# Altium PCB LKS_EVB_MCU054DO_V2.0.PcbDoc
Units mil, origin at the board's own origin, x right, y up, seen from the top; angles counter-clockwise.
Board outline 2625 x 1560 mil, 2 copper layers (Top Layer, Bottom Layer); 34 components, 56 nets, 171 pads, 56 vias.
Unrouted connection lines stored in the file: 4.
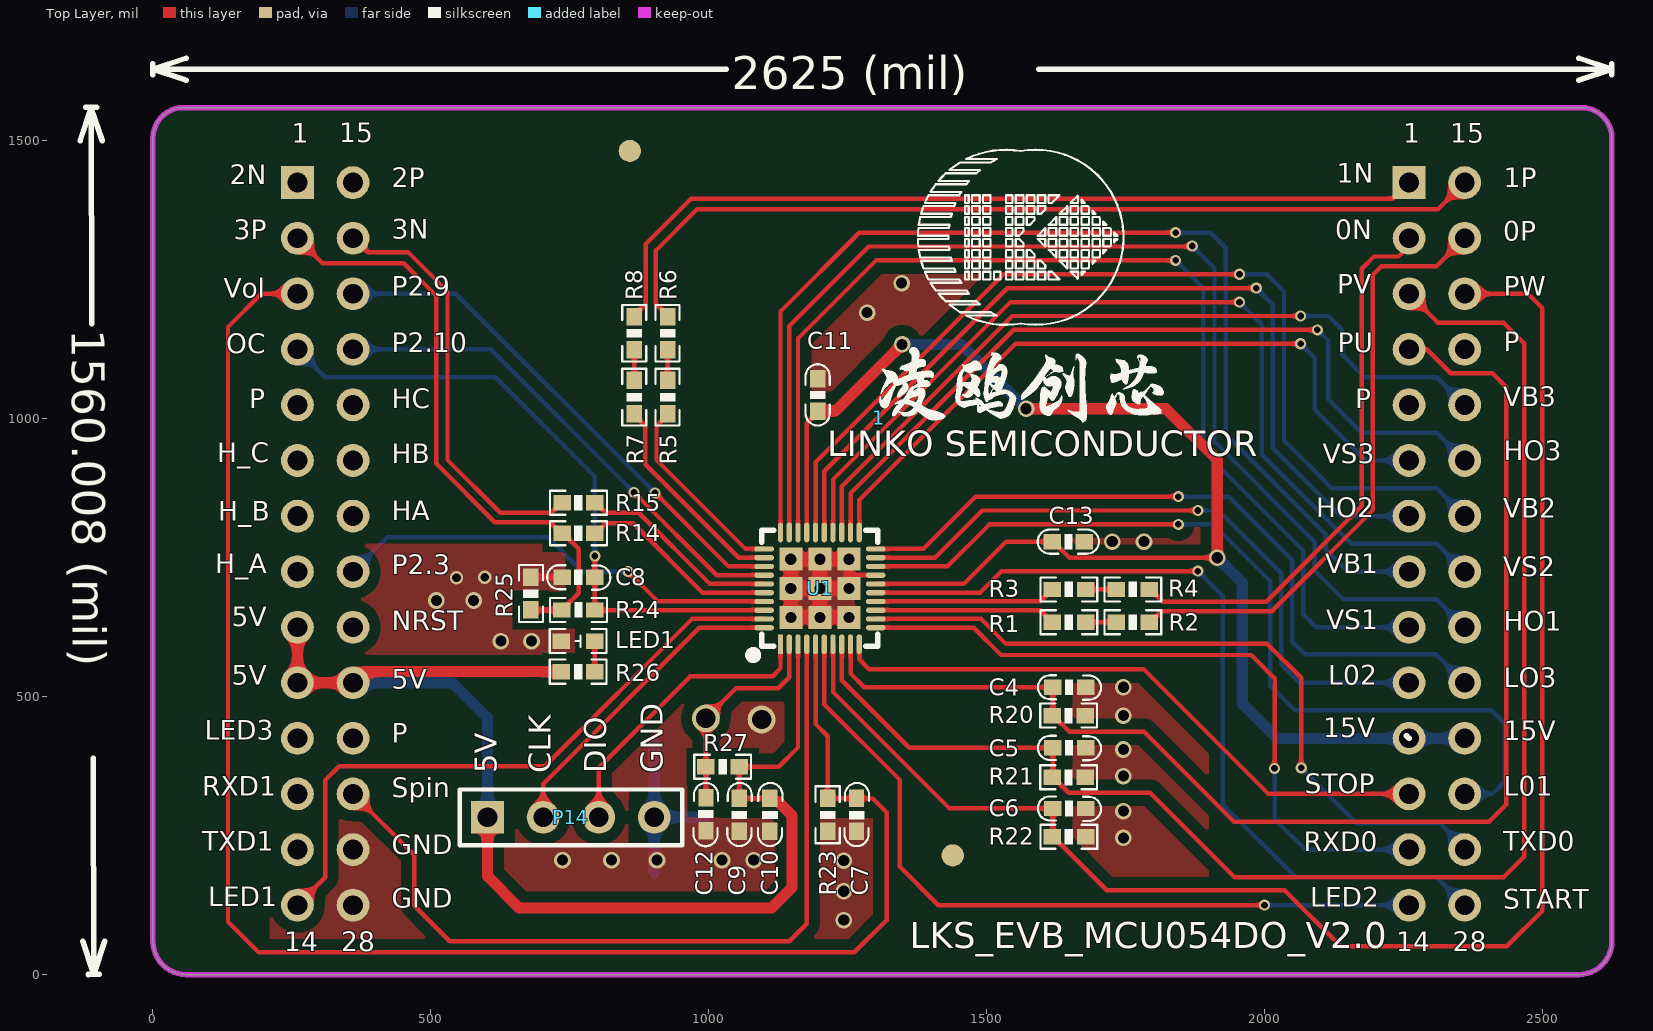
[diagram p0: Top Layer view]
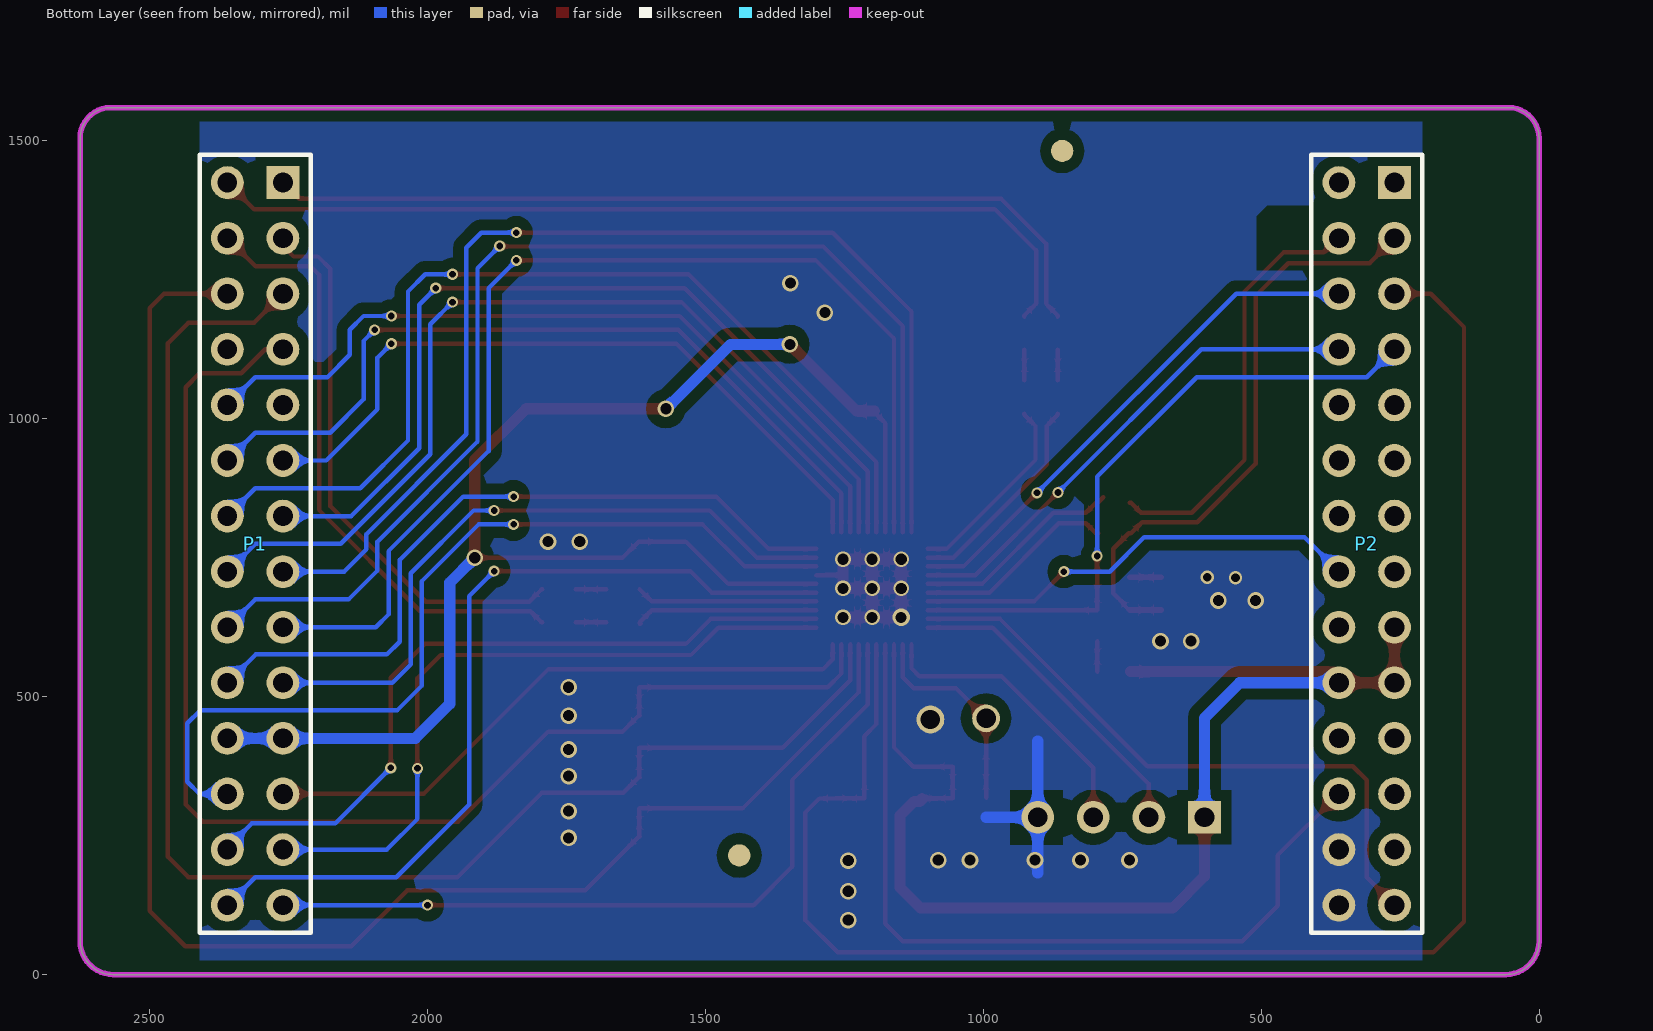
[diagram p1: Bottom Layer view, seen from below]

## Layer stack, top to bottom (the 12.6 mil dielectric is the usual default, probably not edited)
Top Solder: solder mask 0.4, Solder Resist, Dk 3.5
Top Layer: signal copper 1.4
Dielectric1: dielectric 12.6, FR-4, Dk 4.8
Bottom Layer: signal copper 1.4
Bottom Solder: solder mask 0.4, Solder Resist, Dk 3.5

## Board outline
0,60 ccw(c60,60) 60,0 2565,0 ccw(c2565,60) 2625,60 2625,1505 ccw(c2570,1505) 2570,1560 55,1560 ccw(c55,1505) 0,1505

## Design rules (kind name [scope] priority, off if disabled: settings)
Clearance Clearance_1 [InPolygon] p1: gap=20 ignorepadtopadclearanceinfootprint=FALSE
Clearance [All] p2: gap=6 ignorepadtopadclearanceinfootprint=FALSE
ComponentClearance [All] p1: gap=0 collisioncheckmode=3 verticalgap=0 showdistances=FALSE
FabricationTestpoint [(IsPad And (OnTopLayer Or OnBottomLayer))] p1: side=3 testpointundercomponent=TRUE minsize=40 maxsize=100 preferedsize=60 minholesize=0 maxholesize=40 preferedholesize=32 testpointgrid=1 allowsidetop=TRUE allowsidebottom=TRUE usegrid=TRUE gridtolerance=0.01
HoleSize [All] p1: absolutevalues=TRUE maxlimit=100 minlimit=0 maxpercent=80.000 minpercent=20.000
PolygonConnect [All] p1: connectstyle=Direct reliefconductorwidth=30 reliefentries=4 polygonreliefangle="90 Angle" airgapwidth=10
RoutingVias [All] p1: holewidth=28 width=50 viastyle="Through Hole" minholewidth=0 minwidth=10 maxholewidth=28 maxwidth=100
SilkToSolderMaskClearance SilkscreenOverComponentPads [IsPad] p1: minsilkscreentomaskgap=10 clearancetoexposedcopper=TRUE
SolderMaskExpansion [All] p1: expansion=4 istentingtop=FALSE
Width [All] p1: maxlimit=100 minlimit=2 preferedwidth=10
26 further rules are at their usual default settings.

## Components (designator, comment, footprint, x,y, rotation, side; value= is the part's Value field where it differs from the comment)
1 "LKS_sign" LKS_LOGO2 1306,1002 r0 top
C4 "1nF/16V" 0603C#1 1619,517 r0 top
C5 "1nF/16V" 0603C#1 1618.94,408 r0 top
C6 "1nF/16V" 0603C#1 1618.94,299 r0 top
C7 "100nF/50V" 0603C#1 1266,257.8 r90 top
C8 "1nF/50V" 0603C#1 736,715 r0 top
C9 "10uF/10V" 0603C#1 1055,258 r90 top
C10 "100nF/50V" 0603C#1 1110,257.94 r90 top
C11 "4.7uF/25V" 0603C#2 1196,1043 r270 top
C12 "100nF/50V" 0603C#1 995,318 r270 top
C13 "1uF/16V" 0603C#2 1647,779 r0 top
LED1 "LED" "LED 0603R" 765,600 r180 top
P1 "Header 14X2A" HDR2X14_CEN 2260,1425 r270 bottom locked
P2 "Header 14X2A" HDR2X14_CEN 260,1425 r270 bottom locked
P14 "Header 4" HDR1X4 602,283 r0 top
R1 "20K" 0603R#1 1648,634 r180 top value=K
R2 "20K" 0603R#1 1763,634 r180 top value=K
R3 "20K" 0603R#1 1648,693 r180 top value=K
R4 "20K" 0603R#1 1763,693 r180 top value=K
R5 "20K" 0603R#1 926,1039 r270 top value=K
R6 "20K" 0603R#1 926,1154 r270 top value=K
R7 "20K" 0603R#1 866,1039 r270 top value=K
R8 "20K" 0603R#1 866,1154 r270 top value=K
R14 "1K" 0603R#2 736.22,794 r0 top value=K
R15 "1K" 0603R#2 736.17,849 r0 top value=K
R20 "1K" 0603R#2 1618,466 r0 top value=K
R21 "1K" 0603R#2 1618,355 r0 top value=K
R22 "1K" 0603R#1 1648,248 r0 top value=K
R23 "1K" 0603R#2 1214,258 r90 top value=K
R24 "1K" 0603R#2 795,656 r180 top value=K
R25 "10R" 0603R#2 680,656 r90 top value=K
R26 "3.3K" 0603R#1 765,545 r180 top value=330
R27 "20K" 0603R#1 1025,374 r180 top value=K
U1 "LKS32MC054DOF6Q8" QFN40 1200,695 r90 top locked

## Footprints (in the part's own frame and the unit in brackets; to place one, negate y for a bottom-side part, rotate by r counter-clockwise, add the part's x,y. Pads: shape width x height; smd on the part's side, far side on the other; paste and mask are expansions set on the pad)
0603C#1 [mm]
  rect 0.8x0.7 smd: 1(0,0) 2(1.5,0)
  silkscreen extent -0.68,-0.57 2.21,0.55
0603C#2 [mm] "电容"
  rect 0.8x0.7 smd: 1(-0.737,0) 2(0.738,0)
  silkscreen extent -1.4,-0.55 1.4,0.55, body extent -0.8,-0.41 0.8,0.41, height 0.81
0603R#1 [mm] "电阻"
  rect 0.8x0.7 smd: 1(-0.762,0) 2(0.762,0)
  silkscreen extent -1.3,-0.55 1.3,0.55, body extent -0.8,-0.4 0.8,0.4, height 0.45
0603R#2 [mm]
  rect 0.8x0.7 smd: 1(0,0) 2(1.5,0)
  silkscreen extent -0.55,-0.55 2.05,0.55
HDR1X4 [mm] "Connector; Header; 4 Position"
  rect 1.5x1.5 hole 0.9: 1(0,0)
  round 1.5 hole 0.9: 2(2.54,0) 3(5.08,0) 4(7.62,0)
  silkscreen extent -1.27,-1.27 8.89,1.27
HDR2X14_CEN [mm] "Connector; Header; 14x2 Position"
  rect 1.5x1.5 hole 0.9: 1(0,0)
  round 1.5 hole 0.9: 2(2.54,0) 3(5.08,0) 4(7.62,0) 5(10.16,0) 6(12.7,0) 7(15.24,0) 8(17.78,0) 9(20.32,0) 10(22.86,0) 11(25.4,0) 12(27.94,0) 13(30.48,0) 14(33.02,0) 15(0,-2.54) 16(2.54,-2.54) 17(5.08,-2.54) 18(7.62,-2.54) 19(10.16,-2.54) 20(12.7,-2.54) 21(15.24,-2.54) 22(17.78,-2.54) 23(20.32,-2.54) 24(22.86,-2.54) 25(25.4,-2.54) 26(27.94,-2.54) 27(30.48,-2.54) 28(33.02,-2.54)
  silkscreen extent -1.27,-3.81 34.29,1.27
"LED 0603R" [mm] "LED"
  rect 0.8x0.7 smd: 1(-0.762,0) 2(0.762,0)
  silkscreen extent -1.3,-0.55 1.3,0.55, body extent -0.8,-0.4 0.8,0.4, height 0.47
LKS_LOGO2 [mil] "标?"
  silkscreen extent 70,167 440,482
QFN40 [mm] "LINKO-084D"
  rect 1.05x1.05 smd: 0(-1.33,-1.33) 0(-1.33,0) 0(-1.33,1.33) 0(0,1.33) 0(0,0) 0(0,-1.33) 0(1.33,-1.33) 0(1.33,0) 0(1.33,1.33)
  rect 0.9x0.24 smd: 1(-2.55,1.8)
  oval 0.9x0.24 smd: 2(-2.55,1.4) 3(-2.55,1) 4(-2.55,0.6) 5(-2.55,0.2) 6(-2.55,-0.2) 7(-2.55,-0.6) 8(-2.55,-1) 9(-2.55,-1.4) 10(-2.55,-1.8) 21(2.55,-1.8) 22(2.55,-1.4) 23(2.55,-1) 24(2.55,-0.6) 25(2.55,-0.2) 26(2.55,0.2) 27(2.55,0.6) 28(2.55,1) 29(2.55,1.4) 30(2.55,1.8)
  oval 0.24x0.9 smd: 11(-1.8,-2.55) 12(-1.4,-2.55) 13(-1,-2.55) 14(-0.6,-2.55) 15(-0.2,-2.55) 16(0.2,-2.55) 17(0.6,-2.55) 18(1,-2.55) 19(1.4,-2.55) 20(1.8,-2.55) 31(1.8,2.55) 32(1.4,2.55) 33(1,2.55) 34(0.6,2.55) 35(0.2,2.55) 36(-0.2,2.55) 37(-0.6,2.55) 38(-1,2.55) 39(-1.4,2.55) 40(-1.8,2.55)
  silkscreen extent -3.16,-2.65 2.65,3.16, body extent -3,-3 3,3, height 0.9

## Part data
C4 C5 C6 C13: library part CAP, "Capacitor"
C7 C8 C9 C10 C11 C12: library part C, "Capacitor"
LED1: "LED_Light"
P1 P2: "Header, 14-Pin, Dual row"
P14: "Header, 4-Pin"
R1 R2 R3 R4 R5 R6 R7 R8 R14 R15 R20 R21 R22 R23 R24 R25 R26 R27: library part Res, "Resistor"
U1: "芯片"

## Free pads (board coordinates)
  round 50 hole 35: 0(1095,459) 1(995,461)
  round 40 all layers, no hole: 3(858,1482) 5(1439.03,214.44)

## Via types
v1: diameter 30, hole 20, Top Layer to Bottom Layer, 25 vias
v2: diameter 20, hole 12, Top Layer to Bottom Layer, 20 vias
v3: diameter 28, hole 20, Top Layer to Bottom Layer, 8 vias
v4: diameter 23.62, hole 15.75, Top Layer to Bottom Layer, 2 vias
v5: diameter 31.5, hole 19.68, Top Layer to Bottom Layer, 1 vias

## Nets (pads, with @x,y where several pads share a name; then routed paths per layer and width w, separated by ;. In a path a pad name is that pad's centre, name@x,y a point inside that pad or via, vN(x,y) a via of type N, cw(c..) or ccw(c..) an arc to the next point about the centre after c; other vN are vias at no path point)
+5V: C9.2 C10.2 P2.9 P2.10 P2.24 P14.1 R26.2 R27.1 U1.3 | length 2324.2
  Top Layer w8: C10.2@1109.94,317.06 C9.2 R27.1 1126,374 1160.63,408.63 U1.3
  Top Layer w20: P2.9 P2.10 P2.24 380,545 R26.2 ; P14.1 602,177 659,120 1113,120 1150,157 1150,286 1124.75,311.25 1113.78,311.25 1109.94,315.09 C10.2@1109.94,317.06
  Bottom Layer w20: P2.24 539,525 602,462 P14.1
+15V: C11.2 C13.1 P1.11 P1.25 U1.16 U1.27 | length 2623
  Top Layer w8: U1.27 1176.38,992.35 1196,1011.98 C11.2 ; U1.16 1458.87,702.87 1535,779 C13.1 1619.97,779 1648.97,750 v1(1915,750)
  Top Layer w20: C11.2 1227.95,1013.95 v1(1348,1134) ; v1(1571,1018) 1823,1018 1915,926 v1(1915,750)
  Bottom Layer w20: v1(1348,1134) 1455,1134 v1(1571,1018) ; v1(1915,750) 1960,705 1960,487 2022,425 P1.11 P1.25
GND: C4.2 C5.2 C6.2 C7.1 C8.1 C9.1 C10.1 C11.1 C12.2 C13.2 LED1.2 P2.16 P2.27 P2.28 P14.4 pad.0 R15.1 R20.2 R21.2 R22.2 R23.1 R25.2 U1.0 U1.17 | length 1846.6
  Top Layer w8: P2.16 362.1,1325 387.1,1300 459,1300 530,1229 530,926 625,831 716.2,831 734.2,849 R15.1 ; R25.2 R25.2@680.06,715 ; 1252.36,718.62 U1.17
  Top Layer w10: R25.2@680.06,715 C8.1
  Top Layer w20: U1.0@1181.5,642.64 v3(1200,642.64) ; v3(1252.36,642.64) v3(1200,642.64) ; v3(1147.64,747.36) v5(1147.64,642.64) v3(1200,642.64) ; v3(1147.64,747.36) v3(1200,747.36) ; v3(1147.64,747.36) v3(1147.64,695) v3(1200,695) ; v3(1200,642.64) v3(1200,695) ; v3(1200,695) v3(1252.36,695) 1252.36,718.62 v3(1252.36,747.36) v3(1200,747.36) ; v3(1200,695) v3(1200,747.36)
  Bottom Layer w20: 902,183 P14.4 ; 902,420 P14.4 ; 995,283 P14.4
  other v1: 1243,98 1243,150 1243,205 737,206 825,206 907,206 1024,206 1081,206 1746,246 1746,294 1746,357 1746,405 1746,466 1746,517 626,600 681,600 510,673 577,673 1726,779 1783,779 1285,1191 1347,1244
  other v4: 546,714 597,715
HALL_U: P2.8
HALL_V: P2.7
HALL_W: P2.6
HO1: P1.23 U1.29 | length 2143.7
  Top Layer w8: U1.29 1144.88,1166.88 1288,1310 1869,1310 v2(1870,1311)
  Bottom Layer w8: v2(1870,1311) 1910,1271 1910,959 2090,779 2090,727 2142,675 2310,675 P1.23
HO2: P1.7 U1.25 | length 1619.9
  Top Layer w8: U1.25 1207.87,905.87 1537,1235 v2(1985,1235)
  Bottom Layer w8: v2(1985,1235) 2015,1205 2015,947 2137,825 P1.7
HO3: P1.20 U1.22 | length 1456.2
  Top Layer w8: U1.22 1255.12,866.12 1549,1160 v2(2095,1160)
  Bottom Layer w8: v2(2095,1160) 2115,1140 2115,1035 2175,975 2310,975 P1.20
HU: P2.21
HV: P2.20
HW: P2.19
LED1: P2.14 U1.39 | length 1155.4
  Top Layer w8: P2.14 310,175 310,350 335,375 705,375 969.88,639.88 U1.39
LED2: P1.14 U1.6 | length 1401.6
  Top Layer w8: U1.6 1207.87,486.13 1344,350 1344,194 1413,125 v2(2000,125)
  Bottom Layer w8: v2(2000,125) P1.14
LO1: P1.26 U1.18 | length 1607.5
  Top Layer w8: U1.18 1429.37,734.37 1505,810 v2(1845,810)
  Bottom Layer w8: v2(1845,810) 1908,810 2010,708 2010,520 2054,476 2408,476 2432,452 2432,347 2410,325 P1.26
LO2: P1.10 U1.19 | length 1219.2
  Top Layer w8: U1.19 1407.12,750.12 1492,835 v2(1880,835)
  Bottom Layer w8: v2(1880,835) 1917,835 2030,722 2030,558 2063,525 P1.10
LO3: P1.24 U1.20 | length 1323.5
  Top Layer w8: U1.20 1385.87,765.87 1480,860 v2(1845,860)
  Bottom Layer w8: v2(1845,860) 1936,860 2050,746 2050,599 2073,576 2309,576 P1.24
NetLED1_1: LED1.1 R26.1 | length 55
  Top Layer w8: R26.1 LED1.1
NetR1_1: R1.1 R2.2 | length 55
  Top Layer w8: R1.1 R2.2
NetR3_1: R3.1 R4.2 | length 55
  Top Layer w8: R3.1 R4.2
NetR5_1: R5.1 R6.2 | length 55
  Top Layer w8: R5.1 R6.2
NetR7_1: R7.1 R8.2 | length 55
  Top Layer w8: R7.1 R8.2
NRST: C12.1 pad.1 R27.2 U1.2 | length 383.2
  Top Layer w8: C12.1 R27.2 pad.1 1049,515 1125,515 1144.88,534.88 U1.2
OC: C8.2 P2.4 R24.1 U1.38 | length 1174.7
  Top Layer w8: v2(795,753) 795,715.06 C8.2 795,714.94 R24.1 795.37,655.63 U1.38
  Bottom Layer w8: P2.4 310,1075 616,1075 795,896 v2(795,753)
OPA0_IN: R7.2 U1.32 | length 382.4
  Top Layer w8: R7.2 866,1007.03 886,987.03 886,918 1053.88,750.12 U1.32
OPA0_IP: R5.2 U1.31 | length 351.2
  Top Layer w8: R5.2 926,1007.03 906,987.03 906,926 1066.13,765.87 U1.31
OPA1_IN: R15.2 U1.35 | length 378.2
  Top Layer w8: R15.2@784,858.78 793.78,849 R15.2 ; R15.2@797.19,849 815.19,831 874,831 1002.13,702.87 U1.35
OPA1_IP: R14.2 U1.36 | length 365.5
  Top Layer w8: R14.2@793.31,794 R14.2 797.24,794 815.24,812 864,812 988.87,687.13 U1.36
OPA2_IN: R3.2 U1.14 | length 326.6
  Top Layer w8: U1.14 1596.38,671.38 R3.2
OPA2_IP: R1.2 U1.13 | length 328.5
  Top Layer w8: U1.13 1596.37,655.63 R1.2 ; R1.2@1616.03,631 R1.2@1618,631
P2.3: P2.22 U1.37 | length 813.2
  Top Layer w8: v2(855,725) 908.62,671.38 U1.37
  Bottom Layer w8: P2.22 422,787 710.63,787 772.63,725 v2(855,725)
P2.9: P2.17 U1.33 | length 942.8
  Top Layer w8: v2(903.29,866.71) 1035.63,734.37 U1.33
  Bottom Layer w8: P2.17 545,1225 v2(903.29,866.71)
P2.10: P2.18 U1.34 | length 907.9
  Top Layer w8: v2(865.5,867.5) 1014.38,718.62 U1.34
  Bottom Layer w8: P2.18 608,1125 v2(865.5,867.5)
PGND: P1.1 P1.2 P2.1 P2.2 R4.1 R8.1 R14.1 R24.2 R25.1 | length 3623.2
  Top Layer w8: P2.2 305,1280 451,1280 510,1221 510,919 615,814 714.25,814 R14.1@734.25,794 ; R24.2 737.91,656 747.69,665.78 747.69,667.75 766,686.06 766,766.19 738.19,794 R14.1 ; R8.1 866,1185.97 887,1206.97 887,1315 968,1396 2231,1396 P1.1@2237,1402 ; R4.1 1794.97,693 1816.97,671 2003,671 2175,843 2175,1270 2197,1292 2240.9,1292 2245.58,1296.69 2245.58,1296.77 2260,1311.18 P1.2
  Top Layer w10: R25.1 R24.2
PU: C4.1 P1.4 R20.1 U1.9 | length 2341.4
  Top Layer w8: U1.9 1255.12,541.88 1280,517 C4.1 1619,467 R20.1 1619.97,466 1648.97,437 1783,437 1945,275 2404,275 2435,306 2435,1057 2410,1082 2335,1082 2292,1125 P1.4
PV: C5.1 P1.3 R21.1 U1.8 | length 2655.1
  Top Layer w8: U1.8 1239.37,529.63 1361,408 C5.1 1618.94,355.95 R21.1 1619.97,355 1647.97,327 1794,327 1946,175 2430,175 2467,212 2467,1136 2430,1173 2312,1173 P1.3
PW: C6.1 P1.17 R22.1 U1.7 | length 2844.5
  Top Layer w8: U1.7 1223.62,508.38 1433,299 C6.1 1618.94,248.95 R22.1 1619.97,248 1715.97,152 2036,152 2137,51 2436,51 2500,115 2500,1199 2474,1225 P1.17
RXD0: P1.13 U1.11 | length 1273.1
  Top Layer w8: U1.11 1476.87,624.13 1526,575 1976,575 2018,533 v2(2018,371)
  Bottom Layer w8: v2(2018,371) 2018,280 2073,225 P1.13
RXD1: P2.12
SPIN: P2.26 U1.4 | length 1495.7
  Top Layer w8: P2.26 470,215 470,124 534,60 1145,60 1176.38,91.38 U1.4
START1: P1.28 U1.15 | length 1544.3
  Top Layer w8: U1.15 1488.13,687.13 1527,726 v2(1880,726)
  Bottom Layer w8: v2(1880,726) 1925,681 1925,306 2056,175 2310,175 P1.28
STOP1: P1.12 U1.10 | length 1116.9
  Top Layer w8: U1.10 1270.87,567.13 1289,549 1783,549 2007,325 P1.12
SWCLK: P14.2 U1.40 | length 574.1
  Top Layer w8: P14.2 702,343 983.13,624.13 U1.40
SWDIO: P14.3 U1.1 | length 533.8
  Top Layer w8: P14.3 802,372 967,537 1115,537 1129.13,551.13 U1.1
TXD0: P1.27 U1.12 | length 1328.1
  Top Layer w8: U1.12 1490.12,639.88 1535,595 2005,595 2066,534 v2(2066,372)
  Bottom Layer w8: v2(2066,372) 2166,272 2316,272 2360,228 P1.27
TXD1: P2.13
UP-: P2.15
VB1: P1.8 U1.30 | length 2052.7
  Top Layer w8: U1.30 1129.13,1193.13 1271,1335 v2(1840,1335)
  Bottom Layer w8: v2(1840,1335) 1903,1335 1930,1308 1930,972 2110,792 2110,765 2150,725 P1.8
VB2: P1.21 U1.26 | length 1771.6
  Top Layer w8: U1.26 1192.13,921.97 1530.15,1260 v2(1955,1260)
  Bottom Layer w8: v2(1955,1260) 2004,1260 2035,1229 2035,961 2121,875 2310,875 P1.21
VB3: P1.19 U1.23 | length 1423.3
  Top Layer w8: U1.23 1239.37,878.37 1546,1185 v2(2065,1185)
  Bottom Layer w8: v2(2065,1185) 2115,1185 2140,1160 2140,1115 2180,1075 2310,1075 P1.19
VOL_ADC: C7.2 P2.3 R23.2 U1.5 | length 3048.4
  Top Layer w8: P2.3 195,1225 135,1165 135,95 190,40 1262,40 1320,98 1320,292 1295.14,316.86 C7.2 ; U1.5 1192.13,450.87 1214,429 R23.2 C7.2@1265.8,317.06
VP-: P1.15 R6.1 | length 1633.2
  Top Layer w8: R6.1 926,1185.97 905,1206.97 905,1303 979,1377 1166,1377 2312,1377 P1.15
VS1: P1.9 U1.28 | length 2018.5
  Top Layer w8: U1.28 1160.63,1144.63 1301,1285 v2(1840,1285)
  Bottom Layer w8: v2(1840,1285) 1890,1235 1890,942 2070,762 2070,648 2093,625 P1.9
VS2: P1.22 U1.24 | length 1701.9
  Top Layer w8: U1.24 1223.62,890.62 1543,1210 v2(1955,1210)
  Bottom Layer w8: v2(1955,1210) 1995,1170 1995,936 2156,775 2310,775 P1.22
VS3: P1.6 U1.21 | length 1305.5
  Top Layer w8: U1.21 1270.87,853.87 1552,1135 v2(2065,1135)
  Bottom Layer w8: v2(2065,1135) 2090,1110 2090,1017 2182,925 P1.6
WP-: P1.16 R2.1 | length 1101
  Top Layer w8: R2.1 1794.97,634 1814.97,654 2013,654 2195,836 2195,1259 2210.13,1274.13 2309.13,1274.13 P1.16
pads on no net: P1.5 P1.18 P2.5 P2.11 P2.23 P2.25

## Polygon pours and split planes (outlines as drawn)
GND on Bottom Layer "Top Layer-No Net 1" (solid, remove dead copper, pour order 15): 210,1560 210,0 2410,0 2410,1560
GND on Top Layer "NONET_L-01_P-001" (solid, remove dead copper, pour order 16): 210,1560 210,0 2410,0 2410,1560

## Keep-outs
Keep-Out Layer:
  the board outline again, w10

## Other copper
Top Layer:
  pour cut-out: 1900,169 1917,152 2036,152 2036,494 2009,521 1900,521
  pour cut-out: 302.5,1361.94 302.5,775 760,775 760,1360.25
  pour cut-out: 855.62,333 854.84,233 952,233 952,333
Bottom Layer:
  pour cut-out: 303,1384 489,1384 509,1364 509,1266 313,1266 304,1275
  pour cut-out: 856,333 856,254 856,233 952,233 952,333

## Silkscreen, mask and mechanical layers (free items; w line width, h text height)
Top Overlay:
  drawing of 24 lines, arcs and shapes, not listed
  text "2625 (mil)" at 1041.59,1593.01 h60
  text "1N" at 2130.31,1413 h60
  text "2N" at 138,1410 h60
  text "2P" at 430,1405 h60
  text "1P" at 2430,1405 h60
  text "3N" at 429.94,1312 h60
  text "3P" at 145.1,1311 h60
  text "0N" at 2127.59,1311 h60
  text "0P" at 2429.94,1309 h60
  text "PV" at 2131.09,1213 h60
  text "P2.9" at 430,1210 h60
  text "PW" at 2430,1210 h60
  text "Vol" at 127.12,1206 h60
  text "1560.008 (mil)" at -146,1161 h60 r270.18
  text "P" at 2430,1110 h60
  text "P2.10" at 430,1108 h60
  text "PU" at 2131.53,1108 h60
  text "OC" at 132,1106 h60
  text "VB3" at 2429.94,1011 h60
  text "P" at 173.02,1007 h60
  text "HC" at 430,1007 h60
  text "P" at 2163.27,1007 h60
  text "HO3" at 2430,914 h60
  text "H_C" at 115.47,910 h60
  text "HB" at 430,908 h60
  text "VS3" at 2105,908 h60
  text "HO2" at 2092.79,811 h60
  text "VB2" at 2429.94,810 h60
  text "HA" at 430,806 h60
  text "H_B" at 117.3,805 h60
  text "H_A" at 112.03,710 h60
  text "VB1" at 2109,710 h60
  text "P2.3" at 430,709 h60
  text "VS2" at 2429.94,705 h60
  text "5V" at 141.33,615 h60
  text "VS1" at 2111.27,610 h60
  text "NRST" at 430,608 h60
  text "HO1" at 2430,607 h60
  text "5V" at 141.33,510 h60
  text "L02" at 2114.99,510 h60
  text "LO3" at 2430,505 h60
  text "5V" at 429.94,503 h60
  text "15V" at 2105.83,415 h60
  text "LED3" at 92.82,411 h60
  text "15V" at 2430,410 h60
  text "P" at 430,405 h60
  text "5V" at 619,362 h40 r90
  text "CLK" at 716,362 h40 r90
  text "DIO" at 816,362 h40 r90
  text "GND" at 917,362 h40 r90
  text "STOP" at 2072.42,315 h60
  text "RXD1" at 88.44,310 h60
  text "L01" at 2430,310 h60
  text "Spin" at 429.94,307 h60
  text "TXD1" at 88.55,211 h60
  text "TXD0" at 2429.94,211 h60
  text "RXD0" at 2070.98,210 h60
  text "GND" at 430,204.86 h60
  text "LED1" at 99.09,111 h60
  text "LED2" at 2082.08,110 h60
  text "GND" at 430,109 h60
  text "START" at 2429.94,107 h60
  text "LKS_EVB_MCU054DO_V2.0" at 1362,32 h80
Top Solder:
  circle w78: c1439.03,214.44 r17
  circle w78: c858,1482 r17
Mechanical 1:
  the board outline again, w10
